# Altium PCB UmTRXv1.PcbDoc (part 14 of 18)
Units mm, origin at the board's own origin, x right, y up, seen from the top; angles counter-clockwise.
Board outline 172 x 113 mm, 6 copper layers (Top Layer, GND, MidLayer1, Mid-Layer 2, InternalPlane2, Bottom Layer); 766 components, 613 nets, 3008 pads, 1360 vias.
Unrouted connection lines stored in the file: 2.
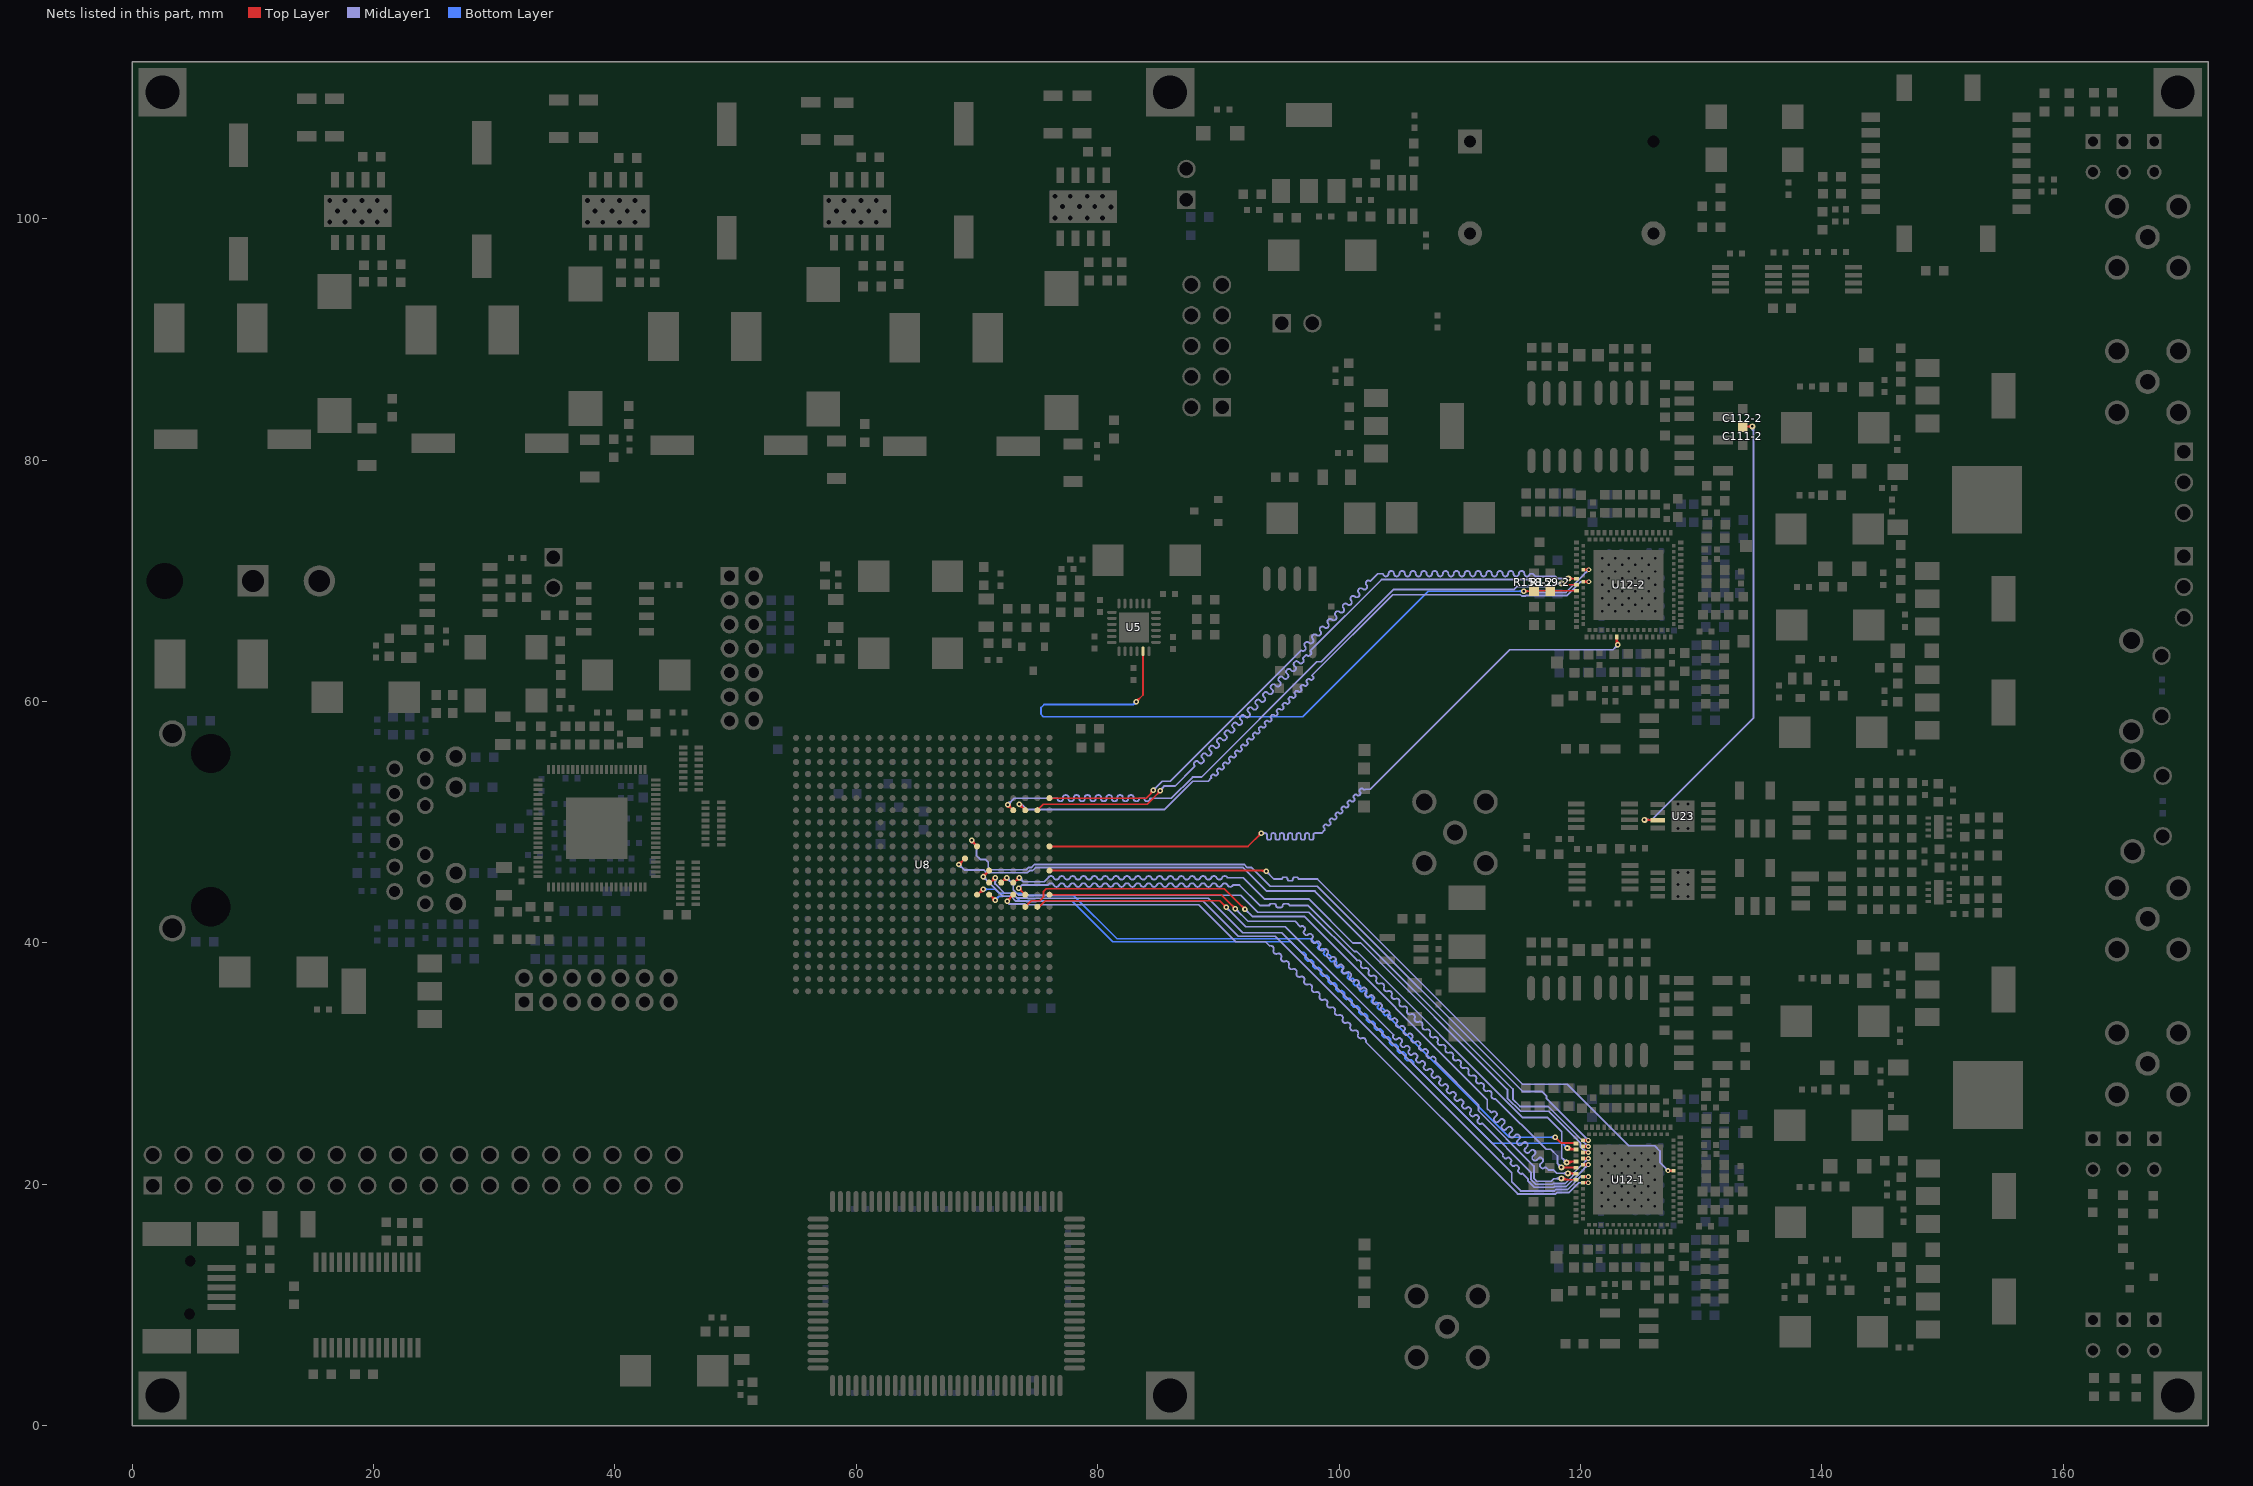
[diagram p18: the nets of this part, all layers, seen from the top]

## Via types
v1: diameter 0.45, hole 0.2, Top Layer to Bottom Layer, tented both sides, 554 vias
v2: diameter 0.5, hole 0.2, Top Layer to Bottom Layer, tented both sides, 468 vias
v3: diameter 0.7, hole 0.3, Top Layer to Bottom Layer, tented both sides, 206 vias
v4: diameter 0.4, hole 0.2, Top Layer to Bottom Layer, tented both sides, 82 vias
v5: diameter 0.8, hole 0.3, Top Layer to Bottom Layer, tented both sides, 16 vias
v6: diameter 0.6, hole 0.25, Top Layer to Bottom Layer, tented both sides, 16 vias
v7: diameter 0.5, hole 0.3, Top Layer to Bottom Layer, tented both sides, 8 vias
v8: diameter 0.7, hole 0.3, Top Layer to Bottom Layer, 4 vias
v9: diameter 0.6, hole 0.3, Top Layer to Bottom Layer, tented both sides, 4 vias
v10: diameter 0.5, hole 0.2, Top Layer to Bottom Layer, 2 vias

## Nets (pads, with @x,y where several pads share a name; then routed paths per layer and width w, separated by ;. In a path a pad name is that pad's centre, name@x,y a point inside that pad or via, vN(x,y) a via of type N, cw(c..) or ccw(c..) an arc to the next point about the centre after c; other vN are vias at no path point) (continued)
RX1D0: U8.J1 U12-1.15 | length 65.9
  Top Layer w0.15: U8.J1@76,44 90.25,44 v1(91.4,42.85) ; v1@91.25,42.85 ccw(c90.888,42.85) 91.144,43.106 ccw(c91.4,43.362) v1@91.4,43 ; v2(118.411,20.495) 118.411,20.458 118.481,20.388 U12-1.15@119.632,20.388 ; v2@118.429,20.513 ccw(c118.73,20.814) 118.73,20.388 ; v2@118.535,20.619 ccw(c119.092,21.176) 119.092,20.388
  MidLayer1 w0.15: v1@91.4,42.7 cw(c91.4,42.338) 91.656,42.594 cw(c91.912,42.85) v1@91.55,42.85 ; v1(91.4,42.85) 92.45,41.8 96.35,41.8 96.795,41.355 ccw(c96.809,41.369) 96.823,41.355 cw(c96.951,41.228) 97.078,41.355 97.141,41.291 cw(c97.014,41.164) 97.141,41.037 97.127,41.023 97.113,41.009 ccw(c97.24,40.881) 97.113,40.754 97.177,40.69 ccw(c97.304,40.818) 97.431,40.69 97.445,40.705 97.46,40.719 cw(c97.587,40.591) 97.714,40.719 97.778,40.655 cw(c97.651,40.528) 97.778,40.4 97.764,40.386 97.75,40.372 ccw(c97.877,40.245) 97.75,40.118 97.813,40.054 ccw(c97.94,40.181) 98.068,40.054 98.082,40.068 98.096,40.082 cw(c98.223,39.955) 98.351,40.082 98.414,40.019 cw(c98.287,39.891) 98.414,39.764 98.4,39.75 98.386,39.736 ccw(c98.513,39.608) 98.386,39.481 98.45,39.418 ccw(c98.577,39.545) 98.704,39.418 98.718,39.432 98.732,39.446 cw(c98.86,39.319) 98.987,39.446 99.051,39.382 cw(c98.923,39.255) 99.051,39.128 99.036,39.114 99.022,39.099 ccw(c99.15,38.972) 99.022,38.845 99.086,38.781 ccw(c99.213,38.908) 99.341,38.781 99.355,38.795 99.369,38.809 cw(c99.496,38.682) 99.623,38.809 99.687,38.746 cw(c99.56,38.619) 99.687,38.491 99.673,38.477 99.659,38.463 ccw(c99.786,38.336) 99.659,38.208 99.722,38.145 ccw(c99.85,38.272) 99.977,38.145 99.991,38.159 100.005,38.173 cw(c100.132,38.046) 100.26,38.173 100.323,38.109 cw(c100.196,37.982) 100.323,37.855 100.309,37.841 100.295,37.827 ccw(c100.422,37.699) 100.295,37.572 100.359,37.508 ccw(c100.486,37.636) 100.613,37.508 100.627,37.523 100.642,37.537 cw(c100.769,37.409) 100.896,37.537 100.96,37.473 cw(c100.833,37.346) 100.96,37.218 100.946,37.204 100.932,37.19 ccw(c101.059,37.063) 100.932,36.936 100.995,36.872 ccw(c101.122,36.999) 101.25,36.872 101.264,36.886 101.278,36.9 cw(c101.405,36.773) 101.533,36.9 101.596,36.837 cw(c101.469,36.709) 101.596,36.582 101.582,36.568 101.568,36.554 ccw(c101.695,36.427) 101.568,36.299 101.632,36.236 ccw(c101.759,36.363) 101.886,36.236 101.9,36.25 101.914,36.264 cw(c102.042,36.137) 102.169,36.264 102.233,36.2 cw(c102.105,36.073) 102.233,35.946 102.218,35.932 102.204,35.917 ccw(c102.332,35.79) 102.204,35.663 102.268,35.599 ccw(c102.395,35.726) 102.523,35.599 102.537,35.613 102.551,35.627 cw(c102.678,35.5) 102.805,35.627 102.869,35.564 cw(c102.742,35.437) 102.869,35.309 102.855,35.295 102.841,35.281 ccw(c102.968,35.154) 102.841,35.026 102.904,34.963 ccw(c103.032,35.09) 103.159,34.963 103.173,34.977 103.187,34.991 cw(c103.314,34.864) 103.442,34.991 103.505,34.927 cw(c103.378,34.8) 103.505,34.673 103.491,34.659 103.477,34.645 ccw(c103.604,34.517) 103.477,34.39 103.541,34.326 ccw(c103.668,34.454) 103.795,34.326 103.809,34.341 103.824,34.355 cw(c103.951,34.227) 104.078,34.355 104.142,34.291 cw(c104.015,34.164) 104.142,34.037 104.128,34.022 104.113,34.008 ccw(c104.241,33.881) 104.113,33.754 104.177,33.69 ccw(c104.304,33.817) 104.432,33.69 104.446,33.704 104.46,33.718 cw(c104.587,33.591) 104.715,33.718 104.778,33.655 cw(c104.651,33.527) 104.778,33.4 104.764,33.386 104.75,33.372 ccw(c104.877,33.245) 104.75,33.117 104.814,33.054 ccw(c104.941,33.181) 105.068,33.054 105.082,33.068 105.096,33.082 cw(c105.224,32.955) 105.351,33.082 105.415,33.018 cw(c105.287,32.891) 105.415,32.764 105.4,32.75 105.386,32.735 ccw(c105.514,32.608) 105.386,32.481 105.45,32.417 ccw(c105.577,32.545) 105.704,32.417 105.733,32.446 cw(c105.86,32.318) 105.987,32.446 106.051,32.382 cw(c105.924,32.255) 106.051,32.127 106.037,32.113 106.023,32.099 ccw(c106.15,31.972) 106.023,31.844 106.086,31.781 ccw(c106.214,31.908) 106.341,31.781 106.355,31.795 106.369,31.809 cw(c106.496,31.682) 106.624,31.809 106.687,31.745 cw(c106.56,31.618) 106.687,31.491 106.673,31.477 106.659,31.463 ccw(c106.786,31.335) 106.659,31.208 106.723,31.144 ccw(c106.85,31.272) 106.977,31.144 106.991,31.159 107.006,31.173 cw(c107.133,31.045) 107.26,31.173 107.324,31.109 cw(c107.196,30.982) 107.324,30.855 107.31,30.84 107.295,30.826 ccw(c107.423,30.699) 107.295,30.572 107.359,30.508 ccw(c107.486,30.635) 107.614,30.508 107.628,30.522 107.642,30.536 cw(c107.769,30.409) 107.897,30.536 107.96,30.473 cw(c107.833,30.345) 107.96,30.218 ccw(c107.974,30.204) 107.96,30.19 111.55,26.6 111.55,26.1 116.143,21.507 116.143,20.511 116.395,20.258 117.577,20.258 117.777,20.458 118.411,20.458 v2(118.411,20.495) ; 117.899,20.458 ccw(c117.899,21.007) v2@118.287,20.619 ; 118.078,20.458 cw(c118.078,20.162) v2@118.287,20.371
RX1D1: U8.L6 U12-1.14 | length 65.2
  Top Layer w0.15: v1(70.5,45.5) U8.L6@71,46 ; v1@70.5,45.675 ccw(c70.5,46.097) 70.799,45.799 ccw(c71.097,45.5) v1@70.675,45.5
  Top Layer w0.2: U12-1.14@120.207,20.638 v4@120.632,20.638 ; v4@120.586,20.567 ccw(c120.416,20.397) 120.416,20.638 ccw(c120.416,20.879) v4@120.586,20.709
  MidLayer1 w0.15: v1@70.5,45.325 cw(c70.5,44.903) 70.799,45.201 cw(c71.097,45.5) v1@70.675,45.5 ; v1(70.5,45.5) 72.125,43.875 72.817,43.875 73.217,43.475 74.067,43.475 74.117,43.425 74.883,43.425 74.908,43.45 88.75,43.45 91.65,40.55 94.7,40.55 114.3,20.95 114.3,20.2 115.042,19.458 115.388,19.458 117.837,19.458 117.949,19.57 118.931,19.57 119.999,20.638 v4(120.657,20.638) ; v4@120.569,20.55 ccw(c120.355,20.336) 120.355,20.638 ccw(c120.355,20.94) v4@120.569,20.726
RX1D2: U8.H3 U12-1.13 | length 65.3
  Top Layer w0.15: U8.H3@74,43 74.5,43.5 75.2,43.5 75.5,43.8 75.5,44.25 75.75,44.5 90.5,44.5 v1(92.2,42.8) ; v1@92.05,42.8 ccw(c91.688,42.8) 91.944,43.056 ccw(c92.2,43.312) v1@92.2,42.95 ; v2(118.961,20.908) 118.981,20.888 U12-1.13@119.632,20.888 ; v2@119.085,20.784 cw(c119.335,20.534) 119.335,20.888 ; v2@119.085,21.032 ccw(c119.432,21.379) U12-1.13@119.432,20.888
  MidLayer1 w0.15: v1@92.2,42.65 cw(c92.2,42.288) 92.456,42.544 cw(c92.712,42.8) v1@92.35,42.8 ; v1(92.2,42.8) 92.8,42.2 97.1,42.2 112.275,27.025 112.275,26.275 112.551,25.999 ccw(c112.636,26.084) 112.721,25.999 cw(c112.848,25.871) 112.976,25.999 113.039,25.935 cw(c112.912,25.808) 113.039,25.681 112.954,25.596 112.869,25.511 ccw(c112.997,25.384) 112.869,25.256 112.933,25.193 ccw(c113.06,25.32) 113.188,25.193 113.357,25.362 cw(c113.485,25.235) 113.612,25.362 113.676,25.299 cw(c113.548,25.171) 113.676,25.044 113.506,24.874 ccw(c113.633,24.747) 113.506,24.62 113.57,24.556 ccw(c113.697,24.683) 113.824,24.556 113.909,24.641 113.994,24.726 cw(c114.121,24.599) 114.248,24.726 114.312,24.662 cw(c114.185,24.535) 114.312,24.408 114.142,24.238 ccw(c114.27,24.111) 114.142,23.983 114.206,23.92 ccw(c114.333,24.047) 114.46,23.92 114.545,24.005 114.63,24.09 cw(c114.757,23.962) 114.885,24.09 114.948,24.026 cw(c114.821,23.899) 114.948,23.771 114.779,23.602 ccw(c114.906,23.474) 114.779,23.347 114.842,23.283 ccw(c114.97,23.411) 115.097,23.283 115.182,23.368 115.267,23.453 cw(c115.394,23.326) 115.521,23.453 115.585,23.389 cw(c115.457,23.262) 115.585,23.135 115.415,22.965 ccw(c115.542,22.838) 115.415,22.711 115.479,22.647 ccw(c115.606,22.774) 115.733,22.647 115.903,22.817 cw(c116.03,22.689) 116.158,22.817 116.221,22.753 cw(c116.094,22.626) 116.221,22.499 116.136,22.414 116.051,22.329 ccw(c116.179,22.202) 116.051,22.074 116.115,22.011 ccw(c116.242,22.138) 116.37,22.011 116.539,22.18 cw(c116.667,22.053) 116.794,22.18 116.858,22.117 cw(c116.73,21.989) 116.858,21.862 116.773,21.777 116.688,21.692 ccw(c116.815,21.565) 116.688,21.438 116.751,21.374 ccw(c116.879,21.502) 117.006,21.374 cw(c117.091,21.289) 117.176,21.374 117.35,21.2 117.75,21.2 118.029,20.92 118.949,20.92 v2(118.961,20.908) ; 118.51,20.92 cw(c118.51,20.457) v2@118.837,20.784 ; 118.568,20.92 ccw(c118.568,21.302) v2@118.837,21.032
RX1D3: U8.K6 U12-1.10 | length 65.1
  Top Layer w0.15: U8.K6@71,45 71.1,45 v1(71.5,45.4) ; v1@71.325,45.4 cw(c70.903,45.4) 71.201,45.101 cw(c71.5,44.803) v1@71.5,45.225
  Top Layer w0.2: U12-1.10@120.207,21.638 v4@120.632,21.638 ; v4@120.586,21.567 ccw(c120.416,21.397) 120.416,21.638 ccw(c120.416,21.879) v4@120.586,21.709
  MidLayer1 w0.15: v1@71.376,45.276 cw(c71.078,44.978) 71.5,44.978 cw(c71.922,44.978) v1@71.624,45.276 ; v1(71.5,45.4) 71.5,44.899 72.274,44.125 72.92,44.125 73.32,43.725 74.17,43.725 74.22,43.675 74.78,43.675 74.805,43.7 89.15,43.7 92,40.85 95.25,40.85 113.6,22.5 ccw(c113.706,22.394) 113.6,22.288 113.706,22.182 ccw(c113.812,22.288) 113.918,22.182 cw(c114.024,22.076) 114.13,22.182 114.236,22.076 cw(c114.13,21.97) 114.236,21.864 ccw(c114.342,21.758) 114.236,21.652 114.342,21.545 ccw(c114.448,21.652) 114.555,21.545 cw(c114.661,21.439) 114.767,21.545 114.873,21.439 cw(c114.767,21.333) 114.873,21.227 ccw(c114.979,21.121) 114.873,21.015 114.979,20.909 ccw(c115.085,21.015) 115.191,20.909 115.643,20.457 115.643,20.304 116.188,19.758 117.784,19.758 117.846,19.82 118.828,19.82 119.895,20.888 119.907,20.888 120.282,21.263 120.282,21.293 120.627,21.638 v4(120.657,21.638) ; 120.392,21.403 cw(c120.657,21.138) v4@120.657,21.513 ; 120.465,21.476 ccw(c120.303,21.638) v4@120.532,21.638
RX1D4: U8.K5 U12-1.11 | length 64.9
  Top Layer w0.15: U8.K5@72,45 72.45,45.45 v1(72.45,45.4) ; U8.K5@72.066,45.066 cw(c72.45,44.682) v1@72.45,45.225 ; 72.187,45.187 ccw(c71.973,45.4) v1@72.275,45.4 ; v2(118.411,21.408) 118.436,21.383 119.627,21.383 U12-1.11@119.632,21.388
  MidLayer1 w0.15: v1@72.45,45.225 cw(c72.45,44.802) 72.749,45.101 cw(c73.047,45.4) v1@72.625,45.4 ; v1(72.45,45.4) 73,44.85 73,44.399 73.424,43.975 74.274,43.975 74.324,43.925 74.676,43.925 74.701,43.95 91.85,43.95 93.25,42.55 97.5,42.55 101.495,38.555 cw(c101.588,38.33) 101.813,38.237 ccw(c102.038,38.144) 102.131,37.919 cw(c102.224,37.693) 102.449,37.601 ccw(c102.675,37.508) 102.768,37.282 cw(c102.86,37.057) 103.086,36.964 ccw(c103.311,36.871) 103.404,36.646 cw(c103.497,36.421) 103.722,36.328 ccw(c103.948,36.235) 104.04,36.01 cw(c104.133,35.784) 104.359,35.691 ccw(c104.584,35.599) 104.677,35.373 cw(c104.77,35.148) 104.995,35.055 ccw(c105.22,34.962) 105.313,34.737 cw(c105.406,34.511) 105.631,34.419 ccw(c105.857,34.326) 105.95,34.1 cw(c106.042,33.875) 106.268,33.782 ccw(c106.493,33.689) 106.586,33.464 cw(c106.679,33.239) 106.904,33.146 ccw(c107.13,33.053) 107.222,32.828 cw(c107.315,32.602) 107.541,32.509 ccw(c107.766,32.417) 107.859,32.191 cw(c107.952,31.966) 108.177,31.873 ccw(c108.402,31.78) 108.495,31.555 cw(c108.588,31.329) 108.813,31.237 ccw(c109.039,31.144) 109.132,30.918 cw(c109.224,30.693) 109.45,30.6 ccw(c109.675,30.507) 109.768,30.282 cw(c109.861,30.057) 110.086,29.964 ccw(c110.312,29.871) 110.404,29.646 cw(c110.497,29.42) 110.723,29.327 ccw(c110.948,29.235) 111.041,29.009 cw(c111.134,28.784) 111.359,28.691 ccw(c111.584,28.598) 111.677,28.373 cw(c111.77,28.147) 111.995,28.055 ccw(c112.221,27.962) 112.314,27.736 cw(c112.406,27.511) 112.632,27.418 ccw(c112.857,27.325) 112.95,27.1 117.15,22.9 117.55,22.9 118.1,22.35 118.1,21.719 v2(118.411,21.408) ; v2@118.236,21.408 ccw(c117.814,21.408) 118.112,21.707 ccw(c118.411,22.006) v2@118.411,21.583
RX1D5: U8.H2 U12-1.8 | length 65
  Top Layer w0.15: U8.H2@75,43 75.15,43 75.65,43.5 90.1,43.5 v1(90.65,42.95) ; v1@90.5,42.95 ccw(c90.138,42.95) 90.394,43.206 ccw(c90.65,43.462) v1@90.65,43.1
  Top Layer w0.2: U12-1.8@120.207,22.138 v4@120.632,22.138 ; v4@120.586,22.067 ccw(c120.416,21.897) 120.416,22.138 ccw(c120.416,22.379) v4@120.586,22.209
  MidLayer1 w0.15: v1@90.65,42.8 cw(c90.65,42.438) 90.906,42.694 cw(c91.162,42.95) v1@90.8,42.95 ; v1(90.65,42.95) 92.25,41.35 95.55,41.35 104.508,32.392 cw(c104.494,32.378) 104.508,32.363 ccw(c104.635,32.236) 104.508,32.109 104.572,32.045 ccw(c104.699,32.173) 104.826,32.045 104.841,32.059 104.855,32.074 cw(c104.982,31.946) 105.109,32.074 105.173,32.01 cw(c105.046,31.883) 105.173,31.755 105.159,31.741 105.145,31.727 ccw(c105.272,31.6) 105.145,31.473 105.208,31.409 ccw(c105.336,31.536) 105.463,31.409 105.477,31.423 105.491,31.437 cw(c105.618,31.31) 105.746,31.437 105.809,31.374 cw(c105.682,31.246) 105.809,31.119 105.795,31.105 105.781,31.091 ccw(c105.908,30.963) 105.781,30.836 105.845,30.773 ccw(c105.972,30.9) 106.099,30.773 106.113,30.787 106.127,30.801 cw(c106.255,30.674) 106.382,30.801 106.446,30.737 cw(c106.318,30.61) 106.446,30.483 106.432,30.468 106.417,30.454 ccw(c106.545,30.327) 106.417,30.2 106.481,30.136 ccw(c106.608,30.263) 106.736,30.136 106.75,30.15 106.764,30.164 cw(c106.891,30.037) 107.018,30.164 107.082,30.101 cw(c106.955,29.973) 107.082,29.846 107.068,29.832 107.054,29.818 ccw(c107.181,29.691) 107.054,29.563 107.117,29.5 ccw(c107.245,29.627) 107.372,29.5 107.386,29.514 107.4,29.528 cw(c107.528,29.401) 107.655,29.528 107.718,29.464 cw(c107.591,29.337) 107.718,29.21 107.704,29.196 107.69,29.182 ccw(c107.817,29.054) 107.69,28.927 107.754,28.863 ccw(c107.881,28.991) 108.008,28.863 108.023,28.877 108.037,28.892 cw(c108.164,28.764) 108.291,28.892 108.355,28.828 cw(c108.228,28.701) 108.355,28.573 108.341,28.559 108.327,28.545 ccw(c108.454,28.418) 108.327,28.291 108.39,28.227 ccw(c108.518,28.354) 108.645,28.227 108.659,28.241 108.673,28.255 cw(c108.8,28.128) 108.928,28.255 108.991,28.192 cw(c108.864,28.064) 108.991,27.937 108.977,27.923 108.963,27.909 ccw(c109.09,27.781) 108.963,27.654 109.027,27.591 ccw(c109.154,27.718) 109.281,27.591 109.295,27.605 109.309,27.619 cw(c109.437,27.492) 109.564,27.619 109.628,27.555 cw(c109.5,27.428) 109.628,27.301 109.614,27.286 109.599,27.272 ccw(c109.727,27.145) 109.599,27.018 109.663,26.954 ccw(c109.79,27.081) 109.918,26.954 109.932,26.968 109.946,26.982 cw(c110.073,26.855) 110.2,26.982 110.264,26.919 cw(c110.137,26.792) 110.264,26.664 110.25,26.65 110.236,26.636 ccw(c110.363,26.509) 110.236,26.381 110.299,26.318 ccw(c110.427,26.445) 110.554,26.318 110.568,26.332 110.582,26.346 cw(c110.71,26.219) 110.837,26.346 110.9,26.282 cw(c110.773,26.155) 110.9,26.028 110.886,26.014 110.872,26 ccw(c110.999,25.872) 110.872,25.745 110.936,25.681 ccw(c111.063,25.809) 111.19,25.681 111.205,25.695 111.219,25.71 cw(c111.346,25.582) 111.473,25.71 111.537,25.646 cw(c111.41,25.519) 111.537,25.391 111.523,25.377 111.509,25.363 ccw(c111.636,25.236) 111.509,25.109 111.572,25.045 ccw(c111.699,25.172) 111.827,25.045 cw(c111.841,25.031) 111.855,25.045 115.893,21.007 115.893,20.407 116.292,20.008 117.68,20.008 117.742,20.07 118.724,20.07 119.386,20.732 119.386,20.897 120.627,22.138 v4(120.657,22.138) ; 120.392,21.903 cw(c120.657,21.638) v4@120.657,22.013 ; 120.465,21.976 ccw(c120.303,22.138) v4@120.532,22.138
RX1D6: U8.J3 U12-1.9 | length 64.9
  Top Layer w0.15: v1@73.45,44.375 cw(c73.45,43.952) 73.749,44.251 cw(c74.047,44.55) v1@73.625,44.55 ; v1(73.45,44.55) U8.J3@74,44 ; v2(118.861,21.808) 118.811,21.758 118.811,21.708 118.991,21.888 U12-1.9@119.632,21.888 ; v2@118.879,21.79 cw(c119.114,21.555) 119.114,21.888 ; v2@118.985,21.684 cw(c119.476,21.193) U12-1.9@119.476,21.888
  MidLayer1 w0.15: v1(73.45,44.55) 73.7,44.8 75.9,44.8 cw(c76.125,44.706) 76.35,44.8 ccw(c76.575,44.894) 76.8,44.8 cw(c77.025,44.706) 77.25,44.8 ccw(c77.475,44.894) 77.7,44.8 cw(c77.925,44.706) 78.15,44.8 ccw(c78.375,44.894) 78.6,44.8 cw(c78.825,44.706) 79.05,44.8 ccw(c79.275,44.894) 79.5,44.8 cw(c79.725,44.706) 79.95,44.8 ccw(c80.175,44.894) 80.4,44.8 cw(c80.625,44.706) 80.85,44.8 ccw(c81.075,44.894) 81.3,44.8 cw(c81.525,44.706) 81.75,44.8 ccw(c81.975,44.894) 82.2,44.8 cw(c82.425,44.706) 82.65,44.8 ccw(c82.875,44.894) 83.1,44.8 cw(c83.325,44.706) 83.55,44.8 ccw(c83.775,44.894) 84,44.8 cw(c84.225,44.706) 84.45,44.8 ccw(c84.675,44.894) 84.9,44.8 cw(c85.125,44.706) 85.35,44.8 ccw(c85.575,44.894) 85.8,44.8 cw(c86.025,44.706) 86.25,44.8 ccw(c86.475,44.894) 86.7,44.8 cw(c86.925,44.706) 87.15,44.8 ccw(c87.375,44.894) 87.6,44.8 cw(c87.825,44.706) 88.05,44.8 ccw(c88.275,44.894) 88.5,44.8 cw(c88.725,44.706) 88.95,44.8 ccw(c89.175,44.894) 89.4,44.8 cw(c89.625,44.706) 89.85,44.8 ccw(c90.075,44.894) 90.3,44.8 cw(c90.525,44.706) 90.75,44.8 ccw(c90.975,44.894) 91.2,44.8 91.75,44.8 93.45,43.1 94.225,43.1 cw(c94.375,43.1) 94.375,43.25 94.625,43.25 cw(c94.625,43.1) 94.775,43.1 ccw(c94.925,43.1) 94.925,42.95 95.175,42.95 ccw(c95.175,43.1) 95.325,43.1 cw(c95.475,43.1) 95.475,43.25 95.725,43.25 cw(c95.725,43.1) 95.875,43.1 97.45,43.1 101.257,39.293 101.45,39.293 115.193,25.55 117.25,25.55 118.45,24.35 118.45,22.219 v2(118.861,21.808) ; v2@118.686,21.808 ccw(c118.263,21.808) 118.562,22.107 ccw(c118.861,22.406) v2@118.861,21.983
RX1D7: U8.K4 U12-1.6 | length 65.3
  Top Layer w0.15: U8.K4@73,45 73.05,45 73.45,45.4 v1(73.5,45.4) ; U8.K4@73.116,45.066 cw(c73.5,44.682) v1@73.5,45.225 ; 73.237,45.187 ccw(c73.023,45.4) v1@73.325,45.4
  Top Layer w0.2: U12-1.6@120.207,22.638 v4@120.632,22.638 ; v4@120.586,22.567 ccw(c120.416,22.397) 120.416,22.638 ccw(c120.416,22.879) v4@120.586,22.709
  MidLayer1 w0.15: v1@73.5,45.225 cw(c73.5,44.802) 73.799,45.101 cw(c74.097,45.4) v1@73.675,45.4 ; v1(73.5,45.4) 73.825,45.075 75.575,45.075 75.9,45.4 cw(c76.125,45.306) 76.35,45.4 ccw(c76.575,45.494) 76.8,45.4 cw(c77.025,45.306) 77.25,45.4 ccw(c77.475,45.494) 77.7,45.4 cw(c77.925,45.306) 78.15,45.4 ccw(c78.375,45.494) 78.6,45.4 cw(c78.825,45.306) 79.05,45.4 ccw(c79.275,45.494) 79.5,45.4 cw(c79.725,45.306) 79.95,45.4 ccw(c80.175,45.494) 80.4,45.4 cw(c80.625,45.306) 80.85,45.4 ccw(c81.075,45.494) 81.3,45.4 cw(c81.525,45.306) 81.75,45.4 ccw(c81.975,45.494) 82.2,45.4 cw(c82.425,45.306) 82.65,45.4 ccw(c82.875,45.494) 83.1,45.4 cw(c83.325,45.306) 83.55,45.4 ccw(c83.775,45.494) 84,45.4 cw(c84.225,45.306) 84.45,45.4 ccw(c84.675,45.494) 84.9,45.4 cw(c85.125,45.306) 85.35,45.4 ccw(c85.575,45.494) 85.8,45.4 cw(c86.025,45.306) 86.25,45.4 ccw(c86.475,45.494) 86.7,45.4 cw(c86.925,45.306) 87.15,45.4 ccw(c87.375,45.494) 87.6,45.4 cw(c87.825,45.306) 88.05,45.4 ccw(c88.275,45.494) 88.5,45.4 cw(c88.725,45.306) 88.95,45.4 ccw(c89.175,45.494) 89.4,45.4 cw(c89.625,45.306) 89.85,45.4 ccw(c90.075,45.494) 90.3,45.4 cw(c90.525,45.306) 90.75,45.4 92.05,45.4 93.8,43.65 97.484,43.65 101.134,40 101.8,40 113.95,27.85 113.95,27.146 115.046,26.05 117.385,26.05 120,23.435 120,23.1 120.462,22.638 v4(120.657,22.638) ; 120.111,22.989 ccw(c120.657,23.536) v4@120.657,22.763 ; 120.367,22.733 ccw(c120.657,23.024) v4@120.657,22.613
RX1D8: U8.J6 U12-1.5 | length 65.7
  Top Layer w0.15: U8.J6@71,44 71.05,44 v1(71.5,43.55) ; v1@71.325,43.55 ccw(c70.903,43.55) 71.201,43.849 ccw(c71.5,44.147) v1@71.5,43.725 ; v2(118.911,23.008) 118.911,22.958 118.981,22.888 U12-1.5@119.632,22.888 ; v2@118.929,23.026 ccw(c119.261,23.358) 119.261,22.888 ; v2@119.035,23.132 ccw(c119.623,23.721) U12-1.5@119.623,22.888
  MidLayer1 w0.15: v2@118.886,22.983 v2(118.911,23.008)
  Bottom Layer w0.15: v1(71.5,43.55) 71.825,43.875 73.17,43.875 73.545,43.5 77.85,43.5 81.25,40.1 96,40.1 96.909,39.191 cw(c97.015,39.085) 97.121,39.191 97.227,39.085 cw(c97.121,38.979) 97.227,38.873 ccw(c97.333,38.767) 97.227,38.661 97.333,38.555 ccw(c97.439,38.661) 97.545,38.555 cw(c97.652,38.448) 97.758,38.555 97.864,38.448 cw(c97.758,38.342) 97.864,38.236 ccw(c97.97,38.13) 97.864,38.024 97.97,37.918 ccw(c98.076,38.024) 98.182,37.918 cw(c98.288,37.812) 98.394,37.918 98.5,37.812 cw(c98.394,37.706) 98.5,37.6 ccw(c98.606,37.494) 98.5,37.388 98.606,37.282 ccw(c98.712,37.388) 98.818,37.282 cw(c98.924,37.176) 99.03,37.282 99.136,37.176 cw(c99.03,37.07) 99.136,36.964 ccw(c99.243,36.857) 99.136,36.751 99.243,36.645 ccw(c99.349,36.751) 99.455,36.645 cw(c99.561,36.539) 99.667,36.645 99.773,36.539 cw(c99.667,36.433) 99.773,36.327 ccw(c99.879,36.221) 99.773,36.115 99.879,36.009 ccw(c99.985,36.115) 100.091,36.009 cw(c100.197,35.903) 100.303,36.009 100.409,35.903 cw(c100.303,35.797) 100.409,35.691 ccw(c100.515,35.585) 100.409,35.479 100.515,35.373 ccw(c100.621,35.479) 100.727,35.373 cw(c100.834,35.266) 100.94,35.373 101.046,35.266 cw(c100.94,35.16) 101.046,35.054 ccw(c101.152,34.948) 101.046,34.842 101.152,34.736 ccw(c101.258,34.842) 101.364,34.736 cw(c101.47,34.63) 101.576,34.736 101.682,34.63 cw(c101.576,34.524) 101.682,34.418 ccw(c101.788,34.312) 101.682,34.206 101.788,34.1 ccw(c101.894,34.206) 102,34.1 cw(c102.106,33.994) 102.212,34.1 102.318,33.994 cw(c102.212,33.888) 102.318,33.782 ccw(c102.425,33.675) 102.318,33.569 102.425,33.463 ccw(c102.531,33.569) 102.637,33.463 cw(c102.743,33.357) 102.849,33.463 102.955,33.357 cw(c102.849,33.251) 102.955,33.145 ccw(c103.061,33.039) 102.955,32.933 103.061,32.827 ccw(c103.167,32.933) 103.273,32.827 cw(c103.379,32.721) 103.485,32.827 103.591,32.721 cw(c103.485,32.615) 103.591,32.509 ccw(c103.697,32.403) 103.591,32.297 103.697,32.191 ccw(c103.803,32.297) 103.909,32.191 cw(c104.016,32.084) 104.122,32.191 104.228,32.084 cw(c104.122,31.978) 104.228,31.872 ccw(c104.334,31.766) 104.228,31.66 104.334,31.554 ccw(c104.44,31.66) 104.546,31.554 cw(c104.652,31.448) 104.758,31.554 104.864,31.448 cw(c104.758,31.342) 104.864,31.236 ccw(c104.97,31.13) 104.864,31.024 104.97,30.918 ccw(c105.076,31.024) 105.182,30.918 cw(c105.288,30.812) 105.394,30.918 105.5,30.812 cw(c105.394,30.706) 105.5,30.6 ccw(c105.606,30.494) 105.5,30.387 105.606,30.281 ccw(c105.713,30.387) 105.819,30.281 cw(c105.925,30.175) 106.031,30.281 106.137,30.175 cw(c106.031,30.069) 106.137,29.963 112.7,23.4 118.519,23.4 v2(118.911,23.008) ; v1@71.5,43.725 ccw(c71.5,44.147) 71.799,43.849 ccw(c72.097,43.55) v1@71.675,43.55 ; v2@118.736,23.008 ccw(c118.313,23.008) 118.612,23.307 ccw(c118.911,23.606) v2@118.911,23.183
RX1D9: U8.M8 U12-1.4 | length 66
  Top Layer w0.15: v1(68.5,46.5) U8.M8@69,47 ; v1@68.5,46.675 ccw(c68.5,47.097) 68.799,46.799 ccw(c69.097,46.5) v1@68.675,46.5
  Top Layer w0.2: U12-1.4@120.207,23.138 v4@120.632,23.138 ; v4@120.586,23.067 ccw(c120.416,22.897) 120.416,23.138 ccw(c120.416,23.379) v4@120.586,23.209
  MidLayer1 w0.15: v1@68.5,46.325 cw(c68.5,45.903) 68.799,46.201 cw(c69.097,46.5) v1@68.675,46.5 ; v1(68.5,46.5) 68.95,46.05 70.551,46.05 70.776,45.825 74.175,45.825 74.35,46 74.596,46 74.846,46.25 92.054,46.25 94.004,44.3 98,44.3 114.4,27.9 114.4,27.05 115,26.45 117.339,26.45 120.25,23.539 120.25,23.515 120.627,23.138 v4(120.657,23.138) ; 120.392,23.373 ccw(c120.657,23.638) v4@120.657,23.263 ; 120.465,23.3 cw(c120.303,23.138) v4@120.532,23.138
RX1D10: U8.J7 U12-1.3 | length 65.5
  Top Layer w0.15: U8.J7@70,44 70.05,44 v1(70.5,44.45) ; v1@70.325,44.45 cw(c69.903,44.45) 70.201,44.151 cw(c70.5,43.853) v1@70.5,44.275 ; v1@117.9,23.75 cw(c117.9,23.388) 118.156,23.644 cw(c118.412,23.9) v1@118.05,23.9 ; v1(117.9,23.9) 118.367,23.433 119.587,23.433 U12-1.3@119.632,23.388
  Bottom Layer w0.15: v1(70.5,44.45) 71.5,44.45 71.825,44.125 73.274,44.125 73.626,44.125 73.725,44.125 73.925,43.925 78.025,43.925 81.6,40.35 97.65,40.35 98.024,39.976 98.031,39.983 cw(c98.13,39.884) 98.229,39.983 98.278,39.934 cw(c98.179,39.835) 98.278,39.736 98.271,39.729 98.264,39.722 ccw(c98.363,39.623) 98.264,39.524 98.314,39.474 ccw(c98.413,39.573) 98.512,39.474 98.519,39.481 98.526,39.488 cw(c98.625,39.389) 98.724,39.488 98.773,39.439 cw(c98.674,39.34) 98.773,39.241 98.766,39.234 98.759,39.227 ccw(c98.858,39.128) 98.759,39.029 98.809,38.979 ccw(c98.908,39.078) 99.007,38.979 99.014,38.986 99.021,38.993 cw(c99.12,38.894) 99.219,38.993 99.268,38.944 cw(c99.169,38.845) 99.268,38.746 99.261,38.739 99.254,38.732 ccw(c99.353,38.633) 99.254,38.534 99.304,38.484 ccw(c99.403,38.583) 99.502,38.484 99.509,38.491 99.516,38.498 cw(c99.615,38.399) 99.714,38.498 99.763,38.449 cw(c99.664,38.35) 99.763,38.251 99.749,38.237 ccw(c99.848,38.138) 99.749,38.039 99.799,37.989 ccw(c99.898,38.088) 99.997,37.989 100.004,37.996 100.011,38.003 cw(c100.11,37.904) 100.209,38.003 100.258,37.954 cw(c100.159,37.855) 100.258,37.756 100.251,37.749 100.244,37.742 ccw(c100.343,37.643) 100.244,37.544 100.294,37.494 ccw(c100.393,37.593) 100.492,37.494 100.499,37.501 100.506,37.508 cw(c100.605,37.409) 100.704,37.508 100.753,37.459 cw(c100.654,37.36) 100.753,37.261 100.746,37.254 100.739,37.247 ccw(c100.838,37.148) 100.739,37.049 100.789,36.999 ccw(c100.888,37.098) 100.987,36.999 100.994,37.006 101.001,37.013 cw(c101.1,36.914) 101.199,37.013 101.248,36.964 cw(c101.149,36.865) 101.248,36.766 101.241,36.759 101.234,36.752 ccw(c101.333,36.653) 101.234,36.554 101.283,36.504 ccw(c101.382,36.603) 101.481,36.504 101.489,36.511 101.496,36.519 cw(c101.595,36.42) 101.694,36.519 101.743,36.469 cw(c101.644,36.37) 101.743,36.271 101.736,36.264 101.729,36.257 ccw(c101.828,36.158) 101.729,36.059 101.778,36.009 ccw(c101.877,36.108) 101.976,36.009 101.991,36.024 cw(c102.09,35.925) 102.189,36.024 102.238,35.974 cw(c102.139,35.875) 102.238,35.776 102.231,35.769 102.224,35.762 ccw(c102.323,35.663) 102.224,35.564 102.273,35.514 ccw(c102.372,35.613) 102.471,35.514 102.479,35.521 102.486,35.529 cw(c102.585,35.43) 102.684,35.529 102.733,35.479 cw(c102.634,35.38) 102.733,35.281 102.726,35.274 102.719,35.267 ccw(c102.818,35.168) 102.719,35.069 102.768,35.019 ccw(c102.867,35.118) 102.966,35.019 102.973,35.027 102.981,35.034 cw(c103.08,34.935) 103.179,35.034 103.228,34.984 cw(c103.129,34.885) 103.228,34.786 103.221,34.779 103.214,34.772 ccw(c103.313,34.673) 103.214,34.574 103.263,34.524 ccw(c103.362,34.623) 103.461,34.524 103.468,34.532 103.476,34.539 cw(c103.575,34.44) 103.674,34.539 103.723,34.489 cw(c103.624,34.39) 103.723,34.291 103.716,34.284 103.709,34.277 ccw(c103.808,34.178) 103.709,34.079 103.758,34.03 ccw(c103.857,34.128) 103.956,34.029 103.963,34.037 103.97,34.044 cw(c104.069,33.945) 104.168,34.044 104.218,33.994 cw(c104.119,33.895) 104.218,33.796 104.211,33.789 114.1,23.9 v1(117.9,23.9) ; v1@70.624,44.326 cw(c70.922,44.028) 70.922,44.45 cw(c70.922,44.872) v1@70.624,44.574 ; v1@117.794,23.794 ccw(c117.538,23.538) 117.538,23.9 ccw(c117.538,24.262) v1@117.794,24.006
RX1D11: U8.N7 U12-1.2 | length 66
  Top Layer w0.15: v1@69.55,48.325 cw(c69.55,48.023) 69.764,48.236 ; v1(69.55,48.5) 69.5,48.5 69.55,48.45 U8.N7@70,48 ; v1@69.725,48.5 ccw(c70.268,48.5) U8.N7@69.884,48.116
  Top Layer w0.2: U12-1.2@120.207,23.638 v4@120.632,23.638 ; v4@120.586,23.567 ccw(c120.416,23.397) 120.416,23.638 ccw(c120.416,23.879) v4@120.586,23.709
  MidLayer1 w0.15: v1@69.55,48.325 cw(c69.55,48.023) 69.764,48.236 ; v1(69.55,48.5) 69.5,48.5 69.95,48.05 69.95,47.25 70.275,46.925 70.676,46.925 70.925,46.676 70.925,46.275 71.125,46.075 74.071,46.075 74.246,46.25 74.493,46.25 74.743,46.5 92.157,46.5 92.407,46.25 92.75,46.25 94.3,44.7 98.2,44.7 115.2,27.7 116.8,27.7 117.175,27.325 117.175,27.12 v4(120.657,23.638) ; v1@69.725,48.5 ccw(c70.267,48.5) 69.884,48.116 ; v4@120.532,23.638 ccw(c120.23,23.638) 120.444,23.851 ccw(c120.657,24.065) v4@120.657,23.763
RX1EN: U8.L1 U12-1.76 | length 65
  Top Layer w0.15: U8.L1@76,46 93.9,46 v1(93.95,45.95) ; 93.467,46 cw(c93.467,45.467) v1@93.844,45.844 ; 93.709,46 ccw(c93.709,46.191) v1@93.844,46.056
  Top Layer w0.2: v4@127.282,21.138 U12-1.76@127.707,21.138 ; v4@127.328,21.067 cw(c127.498,20.897) 127.498,21.138 cw(c127.498,21.379) v4@127.328,21.209
  MidLayer1 w0.15: v1@93.95,45.8 cw(c93.95,45.438) 94.206,45.694 cw(c94.462,45.95) v1@94.1,45.95 ; v1(93.95,45.95) 94.6,45.3 95.275,45.3 cw(c95.425,45.3) 95.425,45.45 95.575,45.45 cw(c95.575,45.3) 95.725,45.3 ccw(c95.875,45.3) 95.875,45.15 96.025,45.15 ccw(c96.025,45.3) 96.175,45.3 cw(c96.325,45.3) 96.325,45.45 96.475,45.45 cw(c96.475,45.3) 96.625,45.3 98.2,45.3 115.2,28.3 118.9,28.3 124,23.2 126.146,23.2 126.582,22.764 126.582,21.813 v4(127.257,21.138) ; v4@127.132,21.138 ccw(c126.83,21.138) 127.044,21.351 ccw(c127.257,21.565) v4@127.257,21.263
RX1IQSEL: U8.J4 U12-1.16 | length 64.4
  Top Layer w0.15: v1(72.5,43.45) 72.5,43.5 U8.J4@73,44 ; v1@72.5,43.625 ccw(c72.5,43.927) 72.713,43.713 ; v1@72.675,43.45 cw(c73.218,43.45) U8.J4@72.834,43.834
  Top Layer w0.2: U12-1.16@120.207,20.138 v4@120.632,20.138 ; v4@120.586,20.067 ccw(c120.416,19.897) 120.416,20.138 ccw(c120.416,20.379) v4@120.586,20.209
  MidLayer1 w0.15: v1(72.5,43.45) 72.5,43.4 72.675,43.225 73.963,43.225 74.013,43.175 83.87,43.175 88.375,43.175 91.45,40.1 93.9,40.1 94.25,39.75 cw(c94.343,39.525) 94.568,39.432 ccw(c94.794,39.339) 94.886,39.114 cw(c94.979,38.888) 95.205,38.795 ccw(c95.43,38.703) 95.523,38.477 cw(c95.616,38.252) 95.841,38.159 ccw(c96.066,38.066) 96.159,37.841 cw(c96.252,37.615) 96.477,37.523 ccw(c96.703,37.43) 96.796,37.204 cw(c96.888,36.979) 97.114,36.886 ccw(c97.339,36.793) 97.432,36.568 cw(c97.525,36.343) 97.75,36.25 ccw(c97.976,36.157) 98.068,35.932 cw(c98.161,35.706) 98.387,35.613 ccw(c98.612,35.521) 98.705,35.295 cw(c98.798,35.07) 99.023,34.977 ccw(c99.248,34.884) 99.341,34.659 cw(c99.434,34.433) 99.659,34.341 ccw(c99.885,34.248) 99.978,34.022 cw(c100.07,33.797) 100.296,33.704 ccw(c100.521,33.611) 100.614,33.386 cw(c100.707,33.161) 100.932,33.068 ccw(c101.158,32.975) 101.25,32.75 cw(c101.343,32.524) 101.569,32.431 ccw(c101.794,32.339) 101.887,32.113 cw(c101.98,31.888) 102.205,31.795 114.792,19.208 115.284,19.208 117.941,19.208 118.053,19.32 119.035,19.32 119.853,20.138 v4(120.657,20.138) ; v4@120.569,20.05 ccw(c120.355,19.836) 120.355,20.138 ccw(c120.355,20.44) v4@120.569,20.226
RX2: C111-2.1 C112-2.2 U23.3 | length 41.7
  Top Layer w0.15: v2@125.4,50.2 126.425,50.2 U23.3@126.45,50.175 ; v2@125.424,50.076 cw(c125.722,49.778) 125.722,50.2 cw(c125.722,50.622) v2@125.424,50.324 ; C112-2.2@133.3,82.8 133.95,82.8 ; v2@134.098,82.714 ccw(c133.95,82.63) 133.95,82.8 ; v2@134.098,82.886 cw(c133.95,82.97) 133.95,82.8 ; v2@134.126,82.676 ccw(c133.828,82.378) 133.828,82.8 ccw(c133.828,83.222) v2@134.126,82.924
  MidLayer1 w0.15: v2@125.4,50.2 125.9,50.2 ; v2@125.424,50.076 cw(c125.722,49.778) 125.722,50.2 cw(c125.722,50.622) v2@125.424,50.324 ; 126,50.2 125.9,50.2 ; v2@134.126,82.676 cw(c133.586,82.136) 134.35,82.136 ; v2@134.232,82.782 cw(c133.948,82.498) 134.35,82.498 ; v2(134.25,82.8) 134.35,82.7 134.35,58.65 125.9,50.2
  other v2: 125.3,50.2
RX2_CLK/2: U8.N1 U12-2.40 | length 64.8
  Top Layer w0.15: U8.N1@76,48 92.45,48 v1(93.55,49.1) ; v1@93.4,49.1 cw(c93.038,49.1) 93.294,48.844 cw(c93.55,48.588) v1@93.55,48.95
  Top Layer w0.2: U12-2.40@122.996,65.253 ccw(c123.653,65.253) v1@123.188,64.788 ; U12-2.40@122.996,65.355 122.996,64.804 v1(123.1,64.7)
  MidLayer1 w0.15: v1(93.55,49.1) 93.885,49.1 ; v1@93.662,49 cw(c93.885,48.801) 93.885,49.1 ; v1@93.662,49.2 ccw(c93.885,49.399) 93.885,49.1 ; 98.775,49.523 98.749,49.548 cw(c98.848,49.647) 98.749,49.746 98.799,49.795 cw(c98.898,49.696) 98.997,49.795 99.022,49.77 ccw(c99.121,49.869) 99.22,49.77 99.27,49.82 ccw(c99.171,49.919) 99.27,50.018 99.244,50.043 cw(c99.343,50.142) 99.244,50.241 99.294,50.29 cw(c99.393,50.191) 99.492,50.29 99.517,50.265 ccw(c99.616,50.364) 99.715,50.265 99.765,50.315 ccw(c99.666,50.414) 99.765,50.513 99.739,50.538 cw(c99.838,50.637) 99.739,50.736 99.789,50.785 cw(c99.888,50.686) 99.987,50.785 100.012,50.76 ccw(c100.111,50.859) 100.21,50.76 100.26,50.81 ccw(c100.161,50.909) 100.26,51.008 100.234,51.033 cw(c100.333,51.132) 100.234,51.231 100.284,51.28 cw(c100.383,51.181) 100.482,51.28 100.507,51.255 ccw(c100.606,51.354) 100.705,51.255 100.755,51.305 ccw(c100.656,51.404) 100.755,51.503 100.729,51.528 cw(c100.828,51.627) 100.729,51.726 100.779,51.775 cw(c100.878,51.676) 100.977,51.775 101.002,51.75 ccw(c101.101,51.849) 101.2,51.75 101.25,51.8 ccw(c101.151,51.899) 101.25,51.998 101.224,52.023 cw(c101.323,52.122) 101.224,52.221 101.274,52.27 cw(c101.373,52.171) 101.472,52.27 101.497,52.245 ccw(c101.596,52.344) 101.695,52.245 101.745,52.295 ccw(c101.646,52.394) 101.745,52.493 101.719,52.518 cw(c101.818,52.617) 101.719,52.716 101.769,52.765 cw(c101.868,52.666) 101.967,52.765 101.992,52.74 ccw(c102.091,52.839) 102.19,52.74 102.59,52.74 114.148,64.298 119.072,64.298 119.074,64.3 120.026,64.3 120.028,64.298 122.698,64.298 v1(123.1,64.7) ; 98.775,49.523 cw(c98.676,49.424) 98.775,49.325 98.55,49.1 98.015,49.1 ccw(c98.015,48.96) 97.875,48.96 97.875,48.69 cw(c97.735,48.69) 97.735,48.55 97.665,48.55 cw(c97.665,48.69) 97.525,48.69 97.525,48.96 ccw(c97.385,48.96) 97.385,49.1 97.315,49.1 ccw(c97.315,48.96) 97.175,48.96 97.175,48.69 cw(c97.035,48.69) 97.035,48.55 96.965,48.55 cw(c96.965,48.69) 96.825,48.69 96.825,48.96 ccw(c96.685,48.96) 96.685,49.1 96.615,49.1 ccw(c96.615,48.96) 96.475,48.96 96.475,48.69 cw(c96.335,48.69) 96.335,48.55 96.265,48.55 cw(c96.265,48.69) 96.125,48.69 96.125,48.96 ccw(c95.985,48.96) 95.985,49.1 95.915,49.1 ccw(c95.915,48.96) 95.775,48.96 95.775,48.69 cw(c95.635,48.69) 95.635,48.55 95.565,48.55 cw(c95.565,48.69) 95.425,48.69 95.425,48.96 ccw(c95.285,48.96) 95.285,49.1 95.215,49.1 ccw(c95.215,48.96) 95.075,48.96 95.075,48.69 cw(c94.935,48.69) 94.935,48.55 94.865,48.55 cw(c94.865,48.69) 94.725,48.69 94.725,48.96 ccw(c94.585,48.96) 94.585,49.1 94.515,49.1 ccw(c94.515,48.96) 94.375,48.96 94.375,48.69 cw(c94.235,48.69) 94.235,48.55 94.165,48.55 cw(c94.165,48.69) 94.025,48.69 94.025,48.96 ccw(c93.885,48.96) 93.885,49.1 ; v1@122.95,64.7 cw(c122.588,64.7) 122.844,64.444 cw(c123.1,64.188) v1@123.1,64.55
RX2CLK: R158-2.2 R159-2.1 U5.17 U12-2.17 | length 64.1
  Top Layer w0.15: v1(83.2,60) 83.75,60.55 U5.17@83.75,64.175 ; v1@83.2,60.15 ccw(c83.2,60.512) 83.456,60.256 ccw(c83.712,60) v1@83.35,60 ; v1(115.3,69.15) R158-2.2@116.15,69.15 116.18,69.18 U12-2.17@119.671,69.18 ; v1@115.406,69.044 cw(c115.662,68.788) 115.662,69.15 cw(c115.662,69.512) v1@115.406,69.256
  Bottom Layer w0.15: v1@83.05,59.997 cw(c82.708,59.992) 82.95,59.75 ; v1@83.197,59.85 ccw(c83.192,59.508) 82.95,59.75 ; v1(83.2,60) 82.95,59.75 ; v1@115.194,69.044 ccw(c114.938,68.788) 114.938,69.15 ccw(c114.938,69.512) v1@115.194,69.256 ; v1(115.3,69.15) 107.4,69.15 97,58.75 75.5,58.75 75.3,58.95 75.3,59.5 75.55,59.75 82.95,59.75
RX2D0: U8.T2 U12-2.15 | length 65.8
  Top Layer w0.15: U8.T2@75,51 75.5,51.5 84.1,51.5 85.2,52.6 v1(85.192,52.608) ; 84.925,52.325 ccw(c84.642,52.608) v1@85.042,52.608 ; 84.963,52.363 cw(c85.192,52.134) v1@85.192,52.458 ; v2(118.45,69.787) 118.45,69.75 118.52,69.68 U12-2.15@119.671,69.68 ; v2@118.468,69.805 ccw(c118.769,70.106) 118.769,69.68 ; v2@118.574,69.911 ccw(c119.131,70.468) 119.131,69.68
  MidLayer1 w0.15: v1(85.192,52.608) v1@85.2,52.6 ; v1@85.192,52.758 ccw(c85.192,52.916) 85.304,52.804 ; v1@85.2,52.6 85.15,52.65 85.5,53 86.4,53 88.01,54.61 ccw(c87.96,54.659) 88.01,54.709 cw(c88.137,54.836) 88.01,54.963 88.073,55.027 cw(c88.201,54.9) 88.328,55.027 88.377,54.977 88.427,54.928 ccw(c88.554,55.055) 88.681,54.928 88.745,54.991 ccw(c88.618,55.119) 88.745,55.246 88.646,55.345 cw(c88.773,55.472) 88.646,55.6 88.71,55.663 cw(c88.837,55.536) 88.964,55.663 89.063,55.564 ccw(c89.19,55.691) 89.318,55.564 89.381,55.628 ccw(c89.254,55.755) 89.381,55.882 89.282,55.981 cw(c89.41,56.109) 89.282,56.236 89.346,56.3 cw(c89.473,56.172) 89.601,56.3 89.7,56.201 ccw(c89.827,56.328) 89.954,56.201 90.018,56.264 ccw(c89.891,56.392) 90.018,56.519 89.968,56.568 89.919,56.618 cw(c90.046,56.745) 89.919,56.872 89.982,56.936 cw(c90.11,56.809) 90.237,56.936 90.336,56.837 ccw(c90.463,56.964) 90.591,56.837 90.654,56.901 ccw(c90.527,57.028) 90.654,57.155 90.605,57.205 90.555,57.254 cw(c90.682,57.381) 90.555,57.509 90.619,57.572 cw(c90.746,57.445) 90.873,57.572 90.972,57.473 ccw(c91.1,57.601) 91.227,57.473 91.291,57.537 ccw(c91.163,57.664) 91.291,57.792 91.192,57.891 cw(c91.319,58.018) 91.192,58.145 91.255,58.209 cw(c91.382,58.081) 91.51,58.209 91.609,58.11 ccw(c91.736,58.237) 91.863,58.11 91.927,58.173 ccw(c91.8,58.301) 91.927,58.428 91.828,58.527 cw(c91.955,58.654) 91.828,58.782 91.892,58.845 cw(c92.019,58.718) 92.146,58.845 92.196,58.796 92.245,58.746 ccw(c92.372,58.873) 92.5,58.746 92.563,58.81 ccw(c92.436,58.937) 92.563,59.064 92.464,59.163 cw(c92.592,59.291) 92.464,59.418 92.528,59.482 cw(c92.655,59.354) 92.783,59.482 92.832,59.432 92.882,59.383 ccw(c93.009,59.51) 93.136,59.383 93.2,59.446 ccw(c93.072,59.573) 93.2,59.701 93.101,59.8 cw(c93.228,59.927) 93.101,60.054 93.164,60.118 cw(c93.292,59.991) 93.419,60.118 93.518,60.019 ccw(c93.645,60.146) 93.773,60.019 93.836,60.083 ccw(c93.709,60.21) 93.836,60.337 93.737,60.436 cw(c93.864,60.563) 93.737,60.691 93.801,60.754 cw(c93.928,60.627) 94.055,60.754 94.154,60.655 ccw(c94.282,60.783) 94.409,60.655 94.473,60.719 ccw(c94.345,60.846) 94.473,60.974 94.423,61.023 94.374,61.073 cw(c94.501,61.2) 94.374,61.327 94.437,61.391 cw(c94.564,61.263) 94.692,61.391 94.791,61.292 ccw(c94.918,61.419) 95.045,61.292 95.109,61.355 ccw(c94.982,61.483) 95.109,61.61 95.059,61.659 95.01,61.709 cw(c95.137,61.836) 95.01,61.963 95.074,62.027 cw(c95.201,61.9) 95.328,62.027 95.427,61.928 ccw(c95.554,62.055) 95.682,61.928 95.745,61.992 ccw(c95.618,62.119) 95.745,62.246 95.646,62.345 cw(c95.774,62.473) 95.646,62.6 95.71,62.664 cw(c95.837,62.536) 95.965,62.664 96.064,62.565 ccw(c96.191,62.692) 96.318,62.565 96.382,62.628 ccw(c96.254,62.755) 96.382,62.883 96.283,62.982 cw(c96.41,63.109) 96.283,63.236 96.346,63.3 cw(c96.474,63.173) 96.601,63.3 96.65,63.25 96.7,63.201 ccw(c96.827,63.328) 96.954,63.201 97.018,63.265 ccw(c96.891,63.392) 97.018,63.519 cw(c97.068,63.569) 97.018,63.618 97.237,63.837 cw(c97.287,63.788) 97.336,63.837 ccw(c97.464,63.965) 97.591,63.837 97.655,63.901 ccw(c97.527,64.028) 97.655,64.156 97.625,64.185 cw(c97.645,64.205) 97.625,64.225 103.512,70.112 115.872,70.112 116.434,69.55 117.616,69.55 117.816,69.75 118.45,69.75 v2(118.45,69.787) ; v1@85.342,52.61 cw(c85.881,52.619) 85.5,53 ; 117.938,69.75 ccw(c117.938,70.299) v2@118.326,69.911 ; 118.117,69.75 cw(c118.117,69.454) v2@118.326,69.663
RX2D1: U8.T3 U12-2.14 | length 65.4
  Top Layer w0.15: v1@73.5,51.325 cw(c73.5,50.903) 73.799,51.201 cw(c74.098,51.5) v1@73.675,51.5 ; v1(73.5,51.5) U8.T3@74,51
  Top Layer w0.2: U12-2.14@120.246,69.93 v4@120.671,69.93 ; v4@120.625,69.859 ccw(c120.455,69.688) 120.455,69.93 ccw(c120.455,70.171) v4@120.625,70.001
  MidLayer1 w0.15: v1@73.5,51.325 cw(c73.5,50.42) 74.14,51.06 ; v1@73.5,51.475 cw(c73.5,50.932) 73.884,51.316 ; v1(73.5,51.5) 73.7,51.5 74.15,51.05 85.5,51.05 86.2,51.75 86.211,51.75 87.861,53.4 89.15,53.4 89.424,53.674 89.417,53.681 cw(c89.516,53.78) 89.417,53.879 89.466,53.928 cw(c89.565,53.829) 89.664,53.928 89.671,53.921 89.678,53.914 ccw(c89.777,54.013) 89.876,53.914 89.926,53.964 ccw(c89.827,54.063) 89.926,54.162 89.919,54.169 89.912,54.176 cw(c90.011,54.275) 89.912,54.374 89.961,54.423 cw(c90.06,54.324) 90.159,54.423 90.166,54.416 90.173,54.409 ccw(c90.272,54.508) 90.371,54.409 90.421,54.459 ccw(c90.322,54.558) 90.421,54.657 90.414,54.664 90.407,54.671 cw(c90.506,54.77) 90.407,54.869 90.456,54.918 cw(c90.555,54.819) 90.654,54.918 90.661,54.911 90.668,54.904 ccw(c90.767,55.003) 90.866,54.904 90.916,54.954 ccw(c90.817,55.053) 90.916,55.152 90.909,55.159 90.902,55.166 cw(c91.001,55.265) 90.902,55.364 90.951,55.413 cw(c91.05,55.314) 91.149,55.413 91.163,55.399 ccw(c91.262,55.498) 91.361,55.399 91.411,55.449 ccw(c91.312,55.548) 91.411,55.647 91.404,55.654 91.397,55.661 cw(c91.496,55.76) 91.397,55.859 91.446,55.908 cw(c91.545,55.809) 91.644,55.908 91.651,55.901 91.658,55.894 ccw(c91.757,55.993) 91.856,55.894 91.906,55.944 ccw(c91.807,56.043) 91.906,56.142 91.899,56.149 91.892,56.156 cw(c91.991,56.255) 91.892,56.354 91.941,56.403 cw(c92.04,56.304) 92.139,56.403 92.146,56.396 92.153,56.389 ccw(c92.252,56.488) 92.351,56.389 92.401,56.439 ccw(c92.302,56.538) 92.401,56.637 92.394,56.644 92.387,56.651 cw(c92.486,56.75) 92.387,56.849 92.436,56.898 cw(c92.535,56.799) 92.634,56.898 92.641,56.891 92.648,56.884 ccw(c92.747,56.983) 92.846,56.884 92.896,56.933 ccw(c92.797,57.032) 92.896,57.131 92.889,57.139 92.881,57.146 cw(c92.98,57.245) 92.881,57.344 92.931,57.393 cw(c93.03,57.294) 93.129,57.393 93.136,57.386 93.143,57.379 ccw(c93.242,57.478) 93.341,57.379 93.391,57.428 ccw(c93.292,57.527) 93.391,57.626 93.376,57.641 cw(c93.475,57.74) 93.376,57.839 93.426,57.888 cw(c93.525,57.789) 93.624,57.888 93.631,57.881 93.638,57.874 ccw(c93.737,57.973) 93.836,57.874 93.886,57.923 ccw(c93.787,58.022) 93.886,58.121 93.879,58.129 93.871,58.136 cw(c93.97,58.235) 93.871,58.334 93.921,58.383 cw(c94.02,58.284) 94.119,58.383 94.126,58.376 94.133,58.369 ccw(c94.232,58.468) 94.331,58.369 94.381,58.418 ccw(c94.282,58.517) 94.381,58.616 94.373,58.623 94.366,58.631 cw(c94.465,58.73) 94.366,58.829 94.416,58.878 cw(c94.515,58.779) 94.614,58.878 94.621,58.871 94.628,58.864 ccw(c94.727,58.963) 94.826,58.864 94.876,58.913 ccw(c94.777,59.012) 94.876,59.111 94.868,59.118 94.861,59.126 cw(c94.96,59.225) 94.861,59.324 94.911,59.373 cw(c95.01,59.274) 95.109,59.373 95.116,59.366 95.123,59.359 ccw(c95.222,59.458) 95.321,59.359 95.371,59.408 ccw(c95.272,59.507) 95.371,59.606 95.363,59.613 95.356,59.621 cw(c95.455,59.719) 95.356,59.818 95.406,59.868 cw(c95.505,59.769) 95.604,59.868 95.618,59.854 ccw(c95.717,59.953) 95.816,59.854 95.865,59.903 ccw(c95.766,60.002) 95.865,60.101 95.858,60.108 95.851,60.115 cw(c95.95,60.214) 95.851,60.313 95.901,60.363 cw(c96,60.264) 96.099,60.363 96.106,60.356 96.113,60.349 ccw(c96.212,60.448) 96.311,60.349 96.36,60.398 ccw(c96.261,60.497) 96.36,60.596 96.353,60.603 96.346,60.61 cw(c96.445,60.709) 96.346,60.808 96.396,60.858 cw(c96.495,60.759) 96.594,60.858 96.601,60.851 96.608,60.844 ccw(c96.707,60.943) 96.806,60.844 96.855,60.893 ccw(c96.756,60.992) 96.855,61.091 96.848,61.098 96.841,61.105 cw(c96.94,61.204) 96.841,61.303 96.891,61.353 cw(c96.99,61.254) 97.089,61.353 97.096,61.346 97.103,61.339 ccw(c97.202,61.438) 97.301,61.339 97.35,61.388 ccw(c97.251,61.487) 97.35,61.586 97.343,61.593 97.336,61.6 cw(c97.435,61.699) 97.336,61.798 97.386,61.848 cw(c97.485,61.749) 97.584,61.848 97.591,61.841 97.598,61.834 ccw(c97.697,61.933) 97.796,61.834 97.845,61.883 ccw(c97.746,61.982) 97.845,62.081 97.755,62.171 104.446,68.862 115.022,68.862 115.134,68.75 115.466,68.75 115.516,68.8 118.908,68.8 120.038,69.93 v4(120.696,69.93) ; v4@120.608,69.841 ccw(c120.394,69.628) 120.394,69.93 ccw(c120.394,70.232) v4@120.608,70.018
RX2D2: U8.U1 U12-2.13 | length 65.4
  Top Layer w0.15: U8.U1@76,52 84.016,52 84.6,52.584 v1(84.6,52.65) ; 84.297,52.282 ccw(c83.929,52.65) v1@84.45,52.65 ; 84.456,52.44 cw(c84.6,52.296) v1@84.6,52.5 ; v2(119,70.2) 119.02,70.18 U12-2.13@119.671,70.18 ; v2@119.124,70.076 cw(c119.374,69.826) 119.374,70.18 ; v2@119.124,70.324 ccw(c119.471,70.671) U12-2.13@119.471,70.18
  MidLayer1 w0.15: v1(84.6,52.65) 85.35,53.4 86,53.4 96.854,64.254 ccw(c97.013,64.413) 97.172,64.572 cw(c97.343,64.72) 97.491,64.891 ccw(c97.65,65.05) 97.809,65.209 cw(c97.979,65.357) 98.127,65.527 ccw(c98.286,65.686) 98.445,65.845 cw(c98.616,65.993) 98.763,66.163 ccw(c98.923,66.323) 99.082,66.482 cw(c99.252,66.629) 99.4,66.8 ccw(c99.559,66.959) 99.718,67.118 cw(c99.888,67.266) 100.036,67.436 ccw(c100.195,67.595) 100.354,67.754 cw(c100.525,67.902) 100.673,68.073 ccw(c100.832,68.232) 100.991,68.391 cw(c101.161,68.539) 101.309,68.709 ccw(c101.468,68.868) 101.627,69.027 cw(c101.798,69.175) 101.945,69.345 ccw(c102.105,69.505) 102.264,69.664 cw(c102.434,69.811) 102.582,69.982 103.2,70.6 103.65,70.6 ccw(c103.875,70.6) 104.1,70.6 cw(c104.325,70.6) 104.55,70.6 ccw(c104.775,70.6) 105,70.6 cw(c105.225,70.6) 105.45,70.6 ccw(c105.675,70.6) 105.9,70.6 cw(c106.125,70.6) 106.35,70.6 ccw(c106.575,70.6) 106.8,70.6 cw(c107.025,70.6) 107.25,70.6 ccw(c107.475,70.6) 107.7,70.6 cw(c107.925,70.6) 108.15,70.6 ccw(c108.375,70.6) 108.6,70.6 cw(c108.825,70.6) 109.05,70.6 ccw(c109.275,70.6) 109.5,70.6 cw(c109.725,70.6) 109.95,70.6 ccw(c110.175,70.6) 110.4,70.6 cw(c110.625,70.6) 110.85,70.6 ccw(c111.075,70.6) 111.3,70.6 cw(c111.525,70.6) 111.75,70.6 ccw(c111.975,70.6) 112.2,70.6 cw(c112.425,70.6) 112.65,70.6 ccw(c112.875,70.6) 113.1,70.6 cw(c113.325,70.6) 113.55,70.6 ccw(c113.775,70.6) 114,70.6 cw(c114.225,70.6) 114.45,70.6 ccw(c114.675,70.6) 114.9,70.6 cw(c115.125,70.6) 115.35,70.6 ccw(c115.575,70.6) 115.8,70.6 116.05,70.6 116.271,70.379 117.901,70.379 118.08,70.2 118.262,70.2 118.274,70.212 118.988,70.212 v2(119,70.2) ; v1@84.6,52.8 ccw(c84.6,53.162) 84.856,52.906 ccw(c85.112,52.65) v1@84.75,52.65 ; 118.549,70.212 cw(c118.549,69.749) v2@118.876,70.076 ; 118.606,70.212 ccw(c118.606,70.594) v2@118.876,70.324
RX2D3: U8.T4 U12-2.10 | length 65.3
  Top Layer w0.15: v1@72.55,51.275 cw(c72.55,50.853) 72.849,51.151 cw(c73.147,51.45) v1@72.725,51.45 ; v1(72.55,51.45) U8.T4@73,51
  Top Layer w0.2: U12-2.10@120.246,70.93 v4@120.671,70.93 ; v4@120.625,70.859 ccw(c120.455,70.688) 120.455,70.93 ccw(c120.455,71.171) v4@120.625,71.001
  MidLayer1 w0.15: v1(72.55,51.45) 73.1,52 76.605,52 cw(c76.605,51.93) 76.675,51.93 ccw(c76.855,51.93) 76.855,51.75 76.945,51.75 ccw(c76.945,51.93) 77.125,51.93 77.125,52.07 cw(c77.305,52.07) 77.305,52.25 77.395,52.25 cw(c77.395,52.07) 77.575,52.07 77.575,51.93 ccw(c77.755,51.93) 77.755,51.75 77.845,51.75 ccw(c77.845,51.93) 78.025,51.93 78.025,52.07 cw(c78.205,52.07) 78.205,52.25 78.295,52.25 cw(c78.295,52.07) 78.475,52.07 78.475,51.93 ccw(c78.655,51.93) 78.655,51.75 78.745,51.75 ccw(c78.745,51.93) 78.925,51.93 78.925,52.07 cw(c79.105,52.07) 79.105,52.25 79.195,52.25 cw(c79.195,52.07) 79.375,52.07 79.375,51.93 ccw(c79.555,51.93) 79.555,51.75 79.645,51.75 ccw(c79.645,51.93) 79.825,51.93 79.825,52.07 cw(c80.005,52.07) 80.005,52.25 80.095,52.25 cw(c80.095,52.07) 80.275,52.07 80.275,51.93 ccw(c80.455,51.93) 80.455,51.75 80.545,51.75 ccw(c80.545,51.93) 80.725,51.93 80.725,52.07 cw(c80.905,52.07) 80.905,52.25 80.995,52.25 cw(c80.995,52.07) 81.175,52.07 81.175,51.93 ccw(c81.355,51.93) 81.355,51.75 81.445,51.75 ccw(c81.445,51.93) 81.625,51.93 81.625,52.07 cw(c81.805,52.07) 81.805,52.25 81.895,52.25 cw(c81.895,52.07) 82.075,52.07 82.075,51.93 ccw(c82.255,51.93) 82.255,51.75 82.345,51.75 ccw(c82.345,51.93) 82.525,51.93 82.525,52.07 cw(c82.705,52.07) 82.705,52.25 82.795,52.25 cw(c82.795,52.07) 82.975,52.07 82.975,51.93 ccw(c83.155,51.93) 83.155,51.75 83.245,51.75 ccw(c83.245,51.93) 83.425,51.93 cw(c83.495,51.93) 83.495,52 83.805,52 cw(c83.805,51.93) 83.875,51.93 ccw(c84.055,51.93) 84.055,51.75 84.145,51.75 ccw(c84.145,51.93) 84.325,51.93 cw(c84.395,51.93) 84.395,52 86.107,52 87.857,53.75 88.6,53.75 98.15,63.3 98.531,63.3 104.531,69.3 114.504,69.3 114.754,69.55 115.727,69.55 116.227,69.05 118.805,69.05 119.934,70.18 119.946,70.18 120.321,70.555 120.321,70.585 120.666,70.93 v4(120.696,70.93) ; v1@72.55,51.625 ccw(c72.55,52.047) 72.849,51.749 ccw(c73.147,51.45) v1@72.725,51.45 ; 120.431,70.695 cw(c120.696,70.43) v4@120.696,70.805 ; 120.504,70.768 ccw(c120.342,70.93) v4@120.571,70.93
